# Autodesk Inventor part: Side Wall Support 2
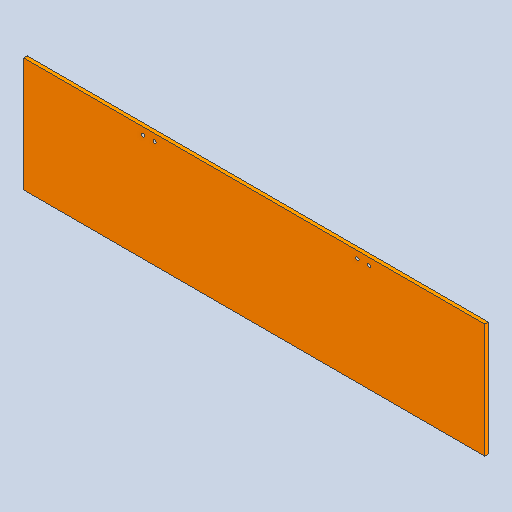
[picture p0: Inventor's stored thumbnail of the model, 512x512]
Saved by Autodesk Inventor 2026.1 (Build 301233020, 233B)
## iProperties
Created: 2026-11
Part Number: Side Wall Support 2
Material: Generic
Document SubType Name: Modeling
Designer: hp
Density: 1 g/cm^3
Appearance: Default
Author: hp
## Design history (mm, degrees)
sketch "Sketch1"
  geometry: L1 (0, 0)-(645, 0); L2 (645, 0)-(645, 160); L3 (645, 160)-(0, 160); L4 (0, 160)-(0, 0)
  constraints: 8 end point, 2 parallel, 1 horizontal, 1 perpendicular
  dimensions: "d0" = 645 distance of L3.end L2.end; "d1" = 160 distance of L2.end L1.end
extrude "Extrusion1" new body sketch "Sketch1" distance "d2" = 5; taper "d3" = 0 deg
sketch "Sketch2"
  geometry: 4 further points
hole "Hole1" sketch "Sketch2" at (-483, 150), (-467, 150), (-183, 150), (-167, 150) diameter "d4" = 4.5; stored, may be unused: countersink angle "d8" = 90 deg, drill point angle "d10" = 0 deg; dims "d5" = 6, "d6" = 4, "d7" = 2, "d9" = 8
body "Solid1"
